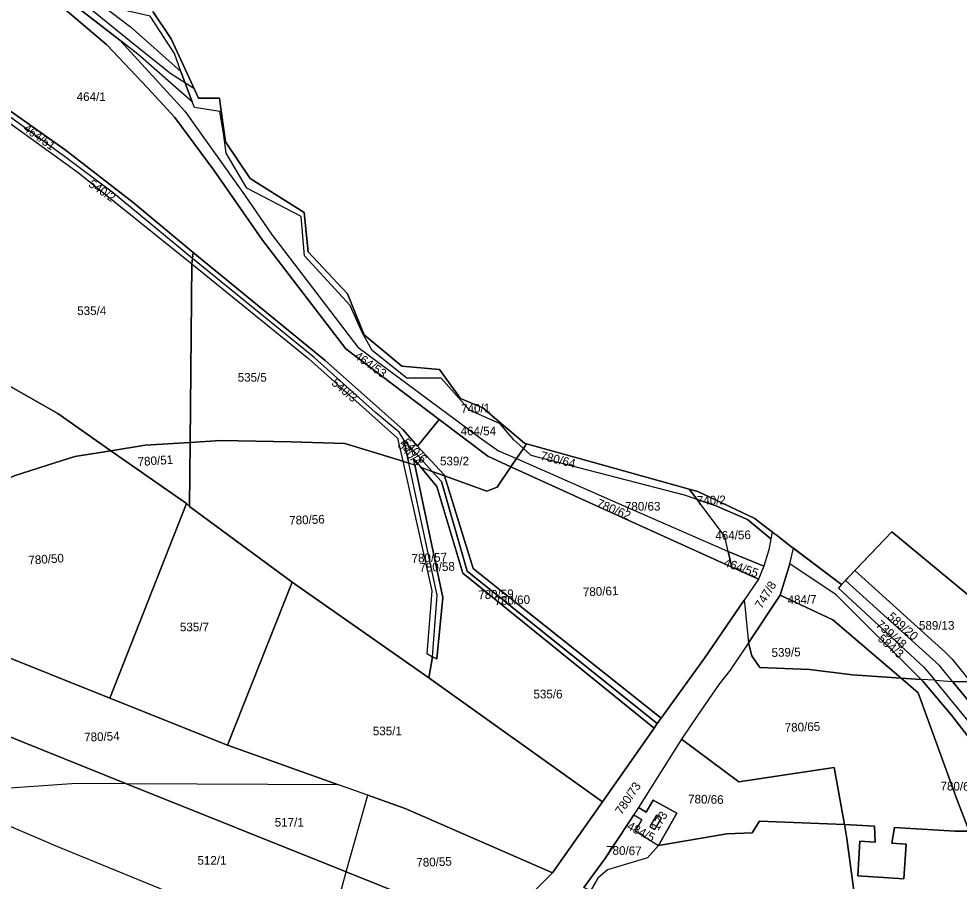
# Model space of a CAD drawing. Extents: x -629983 to -626385, y -1072828 to -1067897.
# Drawn here: x -627261.8 to -626936.7, y -1069848.5 to -1069550.4 of the extents above; entities that cross this region are included whole.
import ezdxf

# ---------------------------------------------------------------- set-up
doc = ezdxf.new("R2010")
doc.units = 0
for name, color, linetype in [('Parcela nároku', 7, 'Continuous'), ('Parcelní číslo', 7, 'Continuous'), ('Plocha PÚ', 7, 'Continuous'), ('Převzatý obvod_Vraclav', 7, 'Continuous'), ('voda', 7, 'Continuous')]:
    doc.layers.add(name, color=color, linetype=linetype)

msp = doc.modelspace()

# ---------------------------------------------------------------- linework, layer by layer
at = {"layer": 'Parcela nároku'}
for points in [[(-627194.37, -1069602.74), (-627177.63, -1069626.85), (-627148.72, -1069664.45), (-627116.5, -1069688.84), (-627123.94, -1069698.07), (-627129.03, -1069692.38), (-627155.86, -1069668.53), (-627201.56, -1069631.19), (-627222.35, -1069613.82), (-627245.87, -1069595.67), (-627265.56, -1069581.74), (-627277.42, -1069573.8), (-627317.22, -1069551.48), (-627328.12, -1069556.45), (-627334.48, -1069509.8), (-627316.09, -1069508.2), (-627271.98, -1069526.74), (-627249.67, -1069543.94), (-627231.46, -1069559.34), (-627217.34, -1069574.26), (-627207.91, -1069584.5)], [(-627235.71, -1069543.56), (-627223.24, -1069553.11), (-627205.83, -1069568.59), (-627201.84, -1069579.11), (-627220.68, -1069562.55), (-627226.86, -1069557.76), (-627251.28, -1069538.83), (-627283.19, -1069513.49), (-627268.22, -1069522.27), (-627246.36, -1069535.48)], [(-627258.69, -1069524.41), (-627268.22, -1069522.27), (-627246.36, -1069535.48), (-627235.71, -1069543.56), (-627223.24, -1069553.11), (-627205.83, -1069568.59), (-627207.95, -1069562.39), (-627216.37, -1069549.5), (-627228.1, -1069546.76), (-627233.41, -1069538.2), (-627242.45, -1069524.53), (-627248.62, -1069521.91)], [(-627204.46, -1069582.29), (-627183.77, -1069611.23), (-627174.51, -1069624.83), (-627144.63, -1069663.86), (-627102.68, -1069694.97), (-627095.92, -1069699.69), (-627089.72, -1069702.42), (-627091.65, -1069705.26), (-627099.6, -1069701.62), (-627116.5, -1069688.84), (-627148.72, -1069664.45), (-627177.63, -1069626.85), (-627194.37, -1069602.74), (-627207.91, -1069584.5), (-627217.34, -1069574.26), (-627231.46, -1069559.34), (-627249.67, -1069543.94), (-627271.98, -1069526.74), (-627274.18, -1069524.76), (-627251.28, -1069538.83), (-627226.86, -1069557.76)], [(-627317.22, -1069551.48), (-627277.42, -1069573.8), (-627265.56, -1069581.74), (-627245.87, -1069595.67), (-627222.35, -1069613.82), (-627201.56, -1069631.19), (-627201.8, -1069633.24), (-627229.1, -1069610.62), (-627246.09, -1069598), (-627266.23, -1069583.3), (-627285.91, -1069570.72), (-627317.17, -1069554.05), (-627327.83, -1069558.62), (-627328.12, -1069556.45)], [(-627095.42, -1069690.37), (-627106, -1069685.67), (-627115.82, -1069674.58), (-627127.62, -1069674.64), (-627139.64, -1069664.99), (-627143.1, -1069658.85), (-627147.21, -1069649.46), (-627163.08, -1069632.32), (-627164.24, -1069618.69), (-627182.98, -1069608.87), (-627190.13, -1069596.83), (-627190.91, -1069590.7), (-627192.35, -1069582.37), (-627201.1, -1069581.07), (-627201.84, -1069579.11), (-627220.68, -1069562.55), (-627226.86, -1069557.76), (-627204.46, -1069582.29), (-627183.77, -1069611.23), (-627174.51, -1069624.83), (-627144.63, -1069663.86), (-627102.68, -1069694.97), (-627095.92, -1069699.69), (-627089.72, -1069702.42), (-627087.33, -1069698.93), (-627090.63, -1069695.89)], [(-627229.1, -1069610.62), (-627246.09, -1069598), (-627266.23, -1069583.3), (-627266.23, -1069585.55), (-627241.35, -1069603.52), (-627202.04, -1069635.13), (-627201.8, -1069633.24)], [(-627266.23, -1069585.55), (-627241.35, -1069603.52), (-627202.04, -1069635.13), (-627202.64, -1069696.79), (-627218.16, -1069697.8), (-627230.03, -1069699.67), (-627248.4, -1069686.8), (-627265.16, -1069677.28), (-627265.26, -1069616.46)], [(-627128.72, -1069695.93), (-627130.35, -1069693.25), (-627138.52, -1069686.49), (-627159.67, -1069667.41), (-627201.8, -1069633.24), (-627202.04, -1069635.13), (-627161.63, -1069667.81), (-627130.84, -1069695.35), (-627129.05, -1069703.33), (-627126.99, -1069703.95)], [(-627201.8, -1069633.24), (-627201.56, -1069631.19), (-627155.86, -1069668.53), (-627129.03, -1069692.38), (-627123.94, -1069698.07), (-627114.7, -1069708.01), (-627114.58, -1069708.4), (-627118.86, -1069706.86), (-627128.72, -1069695.93), (-627130.35, -1069693.25), (-627138.52, -1069686.49), (-627159.67, -1069667.41)], [(-627161.63, -1069667.81), (-627130.84, -1069695.35), (-627129.05, -1069703.33), (-627149.14, -1069697.19), (-627167.71, -1069696.66), (-627192.07, -1069696.11), (-627202.64, -1069696.79), (-627202.04, -1069635.13)], [(-627291.19, -1069665.02), (-627265.16, -1069677.28), (-627248.4, -1069686.8), (-627230.03, -1069699.67), (-627242.51, -1069701.63), (-627251.94, -1069704.66), (-627263.41, -1069708.33), (-627281.71, -1069716.5), (-627302.54, -1069727.27), (-627313.07, -1069724.21)], [(-627116.5, -1069688.84), (-627099.6, -1069701.62), (-627091.65, -1069705.26), (-627096.48, -1069712.33), (-627099.99, -1069713.66), (-627114.58, -1069708.4), (-627114.7, -1069708.01), (-627123.94, -1069698.07)], [(-627124.87, -1069704.6), (-627125.31, -1069702.53), (-627122.87, -1069705.42), (-627118.86, -1069706.86), (-627128.72, -1069695.93), (-627126.99, -1069703.95)], [(-627230.03, -1069699.67), (-627218.16, -1069697.8), (-627202.64, -1069696.79), (-627202.85, -1069718.93), (-627203.9, -1069717.97)], [(-627149.14, -1069697.19), (-627129.05, -1069703.33), (-627118.97, -1069748.1), (-627120.76, -1069769.74), (-627118.81, -1069770.89), (-627120, -1069778.23), (-627167.33, -1069745.11), (-627202.85, -1069718.93), (-627202.64, -1069696.79), (-627192.07, -1069696.11), (-627167.71, -1069696.66)], [(-627084.67, -1069701.38), (-627087.33, -1069698.93), (-627089.72, -1069702.42), (-627056.59, -1069717), (-627018.85, -1069733.52), (-627016.5, -1069734.49), (-627017.66, -1069729.37), (-627027.28, -1069716.55), (-627031.63, -1069715.1), (-627054.85, -1069709.05)], [(-627068.42, -1069702.27), (-627029.99, -1069712.93), (-627027.28, -1069716.55), (-627031.63, -1069715.1), (-627054.85, -1069709.05), (-627084.67, -1069701.38), (-627087.33, -1069698.93), (-627086.24, -1069697.32)], [(-627281.71, -1069716.5), (-627263.41, -1069708.33), (-627251.94, -1069704.66), (-627242.51, -1069701.63), (-627230.03, -1069699.67), (-627203.9, -1069717.97), (-627230.37, -1069785.28), (-627292.84, -1069760.27), (-627294.17, -1069729.71), (-627302.54, -1069727.27)], [(-627091.65, -1069705.26), (-627089.72, -1069702.42), (-627056.59, -1069717), (-627018.85, -1069733.52), (-627016.5, -1069734.49), (-627015.27, -1069739.96), (-627062.1, -1069718.79)], [(-627118.97, -1069748.1), (-627120.76, -1069769.74), (-627118.81, -1069770.89), (-627117.15, -1069749.57), (-627126.99, -1069703.95), (-627129.05, -1069703.33)], [(-627118.81, -1069770.89), (-627117.15, -1069749.57), (-627126.99, -1069703.95), (-627124.87, -1069704.6), (-627115.21, -1069750.43), (-627117.27, -1069771.62)], [(-627122.87, -1069705.42), (-627117.24, -1069712.08), (-627108.34, -1069741.96), (-627042.19, -1069795.61), (-627059.96, -1069821.05), (-627120, -1069778.23), (-627118.81, -1069770.89), (-627117.27, -1069771.62), (-627115.21, -1069750.43), (-627124.87, -1069704.6), (-627125.31, -1069702.53)], [(-627106.85, -1069741.29), (-627041.07, -1069794.04), (-627042.19, -1069795.61), (-627108.34, -1069741.96), (-627117.24, -1069712.08), (-627122.87, -1069705.42), (-627118.86, -1069706.86), (-627115.73, -1069710.33)], [(-627015.27, -1069739.96), (-627006.03, -1069744.14), (-627011, -1069751.36), (-627024.78, -1069771.39), (-627039.76, -1069792.2), (-627094.34, -1069748.74), (-627104.74, -1069740.43), (-627114.58, -1069708.4), (-627099.99, -1069713.66), (-627096.48, -1069712.33), (-627091.65, -1069705.26), (-627062.1, -1069718.79)], [(-627118.86, -1069706.86), (-627114.58, -1069708.4), (-627104.74, -1069740.43), (-627094.34, -1069748.74), (-627039.76, -1069792.2), (-627041.07, -1069794.04), (-627106.85, -1069741.29), (-627115.73, -1069710.33)], [(-627029.99, -1069712.93), (-627027.09, -1069713.74), (-627007.36, -1069723.11), (-627005.01, -1069724.92), (-627001.28, -1069727.78), (-627001.75, -1069730.15), (-627009.83, -1069723.47), (-627020.99, -1069718.65), (-627027.28, -1069716.55)], [(-627202.85, -1069718.93), (-627167.33, -1069745.11), (-627189.71, -1069801.53), (-627230.37, -1069785.28), (-627203.9, -1069717.97)], [(-627020.99, -1069718.65), (-627009.83, -1069723.47), (-627001.75, -1069730.15), (-627002.5, -1069733.98), (-627004.25, -1069739.57), (-627016.5, -1069734.49), (-627017.66, -1069729.37), (-627027.28, -1069716.55)], [(-626993.96, -1069733.38), (-626994.96, -1069732.63), (-626997.8, -1069730.45), (-626999.93, -1069728.82), (-627000.36, -1069728.49), (-627001.28, -1069727.78), (-627001.75, -1069730.15), (-627002.5, -1069733.98), (-627004.25, -1069739.57), (-627006.03, -1069744.14), (-627011, -1069751.36), (-627010.81, -1069753.22), (-627009.77, -1069763.93), (-627009.55, -1069766.12), (-626998.59, -1069749.67), (-626995.22, -1069738.78)], [(-626959.97, -1069727.67), (-626972.76, -1069741.15), (-626941.46, -1069769.32), (-626939.04, -1069771.72), (-626932.72, -1069779.61), (-626917.9, -1069779.99), (-626910.52, -1069780.62), (-626918.56, -1069767.16), (-626927.26, -1069754.77)], [(-627016.5, -1069734.49), (-627004.25, -1069739.57), (-627006.03, -1069744.14), (-627015.27, -1069739.96)], [(-626978.44, -1069747.22), (-626948.86, -1069774.47), (-626945.1, -1069779.05), (-626949.8, -1069778.74), (-626979.25, -1069749.48), (-626995.22, -1069738.78), (-626993.96, -1069733.38), (-626977.33, -1069745.97)], [(-626949.8, -1069778.74), (-626979.25, -1069749.48), (-626995.22, -1069738.78), (-626998.59, -1069749.67), (-626980.4, -1069758.15), (-626956.76, -1069778.29)], [(-626941.46, -1069769.32), (-626939.04, -1069771.72), (-626932.72, -1069779.61), (-626938.99, -1069779.44), (-626943.46, -1069773.97), (-626976.01, -1069744.57), (-626972.76, -1069741.15)], [(-626976.01, -1069744.57), (-626977.33, -1069745.97), (-626978.44, -1069747.22), (-626948.86, -1069774.47), (-626945.1, -1069779.05), (-626938.99, -1069779.44), (-626943.46, -1069773.97)], [(-627120, -1069778.23), (-627059.96, -1069821.05), (-627077.28, -1069845.64), (-627128.21, -1069823.36), (-627141.19, -1069818.75), (-627151.32, -1069815.16), (-627189.71, -1069801.53), (-627167.33, -1069745.11)], [(-626998.59, -1069749.67), (-627009.55, -1069766.12), (-627008.4, -1069770.6), (-627005.63, -1069774.64), (-626988.44, -1069775.32), (-626973.5, -1069777.2), (-626956.76, -1069778.29), (-626980.4, -1069758.15)], [(-627230.37, -1069785.28), (-627189.71, -1069801.53), (-627151.32, -1069815.16), (-627224.57, -1069814.81), (-627281.95, -1069791.81), (-627289.72, -1069770.53), (-627292.84, -1069760.27)], [(-627015.81, -1069775.51), (-627019.72, -1069780.51), (-627027.18, -1069791.27), (-627032.66, -1069799.39), (-627012.86, -1069814.18), (-626979.87, -1069809.23), (-626976.36, -1069828.87), (-626965.93, -1069829.51), (-626965.75, -1069834.99), (-626970.99, -1069834.66), (-626971.74, -1069846.69), (-626955.77, -1069847.69), (-626955.02, -1069835.66), (-626959.98, -1069835.35), (-626958.99, -1069829.94), (-626938.2, -1069831.22), (-626933.22, -1069831.22), (-626937.47, -1069820.18), (-626950.84, -1069783.33), (-626956.76, -1069778.29), (-626973.5, -1069777.2), (-626988.44, -1069775.32), (-627005.63, -1069774.64), (-627008.4, -1069770.6), (-627009.55, -1069766.12)], [(-626920.52, -1069815.29), (-626939.29, -1069791.15), (-626949.21, -1069779.33), (-626949.8, -1069778.74), (-626956.76, -1069778.29), (-626950.84, -1069783.33), (-626937.47, -1069820.18), (-626933.22, -1069831.22), (-626927.26, -1069831.22), (-626918.28, -1069831.86)], [(-626913.9, -1069832.18), (-626914.03, -1069830.33), (-626915.9, -1069814.62), (-626945.1, -1069779.05), (-626949.8, -1069778.74), (-626949.21, -1069779.33), (-626939.29, -1069791.15), (-626920.52, -1069815.29), (-626918.28, -1069831.86)], [(-626945.1, -1069779.05), (-626938.99, -1069779.44), (-626929.34, -1069791.26), (-626911.78, -1069813.19), (-626909.69, -1069832.48), (-626913.9, -1069832.18), (-626914.03, -1069830.33), (-626915.9, -1069814.62)], [(-626906.83, -1069812.73), (-626900.65, -1069834.25), (-626905.52, -1069832.84), (-626911.78, -1069813.19), (-626929.34, -1069791.26), (-626938.99, -1069779.44), (-626932.72, -1069779.61), (-626928.52, -1069784.84), (-626909.14, -1069809.25)], [(-627281.95, -1069791.81), (-627224.57, -1069814.81), (-627241.92, -1069814.72), (-627271.63, -1069816.83)], [(-626976.36, -1069828.87), (-626979.87, -1069809.23), (-627012.86, -1069814.18), (-627032.66, -1069799.39), (-627047.6, -1069823.01), (-627044.92, -1069824.67), (-627042.48, -1069820.54), (-627034.32, -1069824.97), (-627040.67, -1069836.11), (-627016.96, -1069832.15), (-627008.21, -1069831.82), (-627005.67, -1069827.71)], [(-627241.92, -1069814.72), (-627271.63, -1069816.83), (-627267.94, -1069825.76), (-627267.83, -1069828.17), (-627248.42, -1069836.5), (-627155.18, -1069874.63), (-627154, -1069869.04), (-627150.4, -1069851.72), (-627148.6, -1069845.26), (-627224.57, -1069814.81)], [(-627151.32, -1069815.16), (-627224.57, -1069814.81), (-627148.6, -1069845.26), (-627141.19, -1069818.75)], [(-627128.21, -1069823.36), (-627077.28, -1069845.64), (-627090.95, -1069859.46), (-627098.75, -1069866.3), (-627124.51, -1069854.91), (-627148.6, -1069845.26), (-627141.19, -1069818.75)], [(-627047.6, -1069823.01), (-627049.2, -1069825.55), (-627046.42, -1069827.19), (-627048.74, -1069831.11), (-627040.67, -1069836.11), (-627034.32, -1069824.97), (-627042.48, -1069820.54), (-627044.92, -1069824.67)], [(-627059.25, -1069840.82), (-627050.65, -1069827.83), (-627049.2, -1069825.55), (-627046.42, -1069827.19), (-627048.74, -1069831.11), (-627040.67, -1069836.11), (-627044.48, -1069840.42), (-627058.25, -1069844.55), (-627061.64, -1069847.48), (-627064.17, -1069851.84), (-627066.48, -1069850.71)], [(-627043.6, -1069829.61), (-627041.92, -1069830.59), (-627039.65, -1069826.69), (-627041.33, -1069825.7)], [(-627043.6, -1069829.61), (-627041.92, -1069830.59), (-627039.65, -1069826.69), (-627041.33, -1069825.7)], [(-627267.83, -1069828.17), (-627248.42, -1069836.5), (-627155.18, -1069874.63), (-627159.39, -1069894.65), (-627163.63, -1069926.9), (-627217.96, -1069905.51), (-627279.93, -1069882.21), (-627274.63, -1069868.47), (-627269.77, -1069852.06)], [(-627005.67, -1069827.71), (-627008.21, -1069831.82), (-627016.96, -1069832.15), (-627040.67, -1069836.11), (-627044.48, -1069840.42), (-627058.25, -1069844.55), (-627061.64, -1069847.48), (-627064.17, -1069851.84), (-627010.49, -1069878.16), (-626966.86, -1069898.03), (-626975.49, -1069833.73), (-626976.36, -1069828.87)], [(-626955.02, -1069835.66), (-626955.77, -1069847.69), (-626971.74, -1069846.69), (-626970.99, -1069834.66), (-626965.75, -1069834.99), (-626965.93, -1069829.51), (-626976.36, -1069828.87), (-626975.49, -1069833.73), (-626966.86, -1069898.03), (-626939.89, -1069913.2), (-626931.2, -1069914.54), (-626927.45, -1069886.65), (-626924.22, -1069854.62), (-626933.22, -1069831.22), (-626938.2, -1069831.22), (-626958.99, -1069829.94), (-626959.98, -1069835.35)], [(-627154, -1069869.04), (-627150.4, -1069851.72), (-627148.6, -1069845.26), (-627124.51, -1069854.91), (-627098.75, -1069866.3), (-627116.79, -1069882.11), (-627123.18, -1069887.72), (-627155.18, -1069874.63)]]:
    msp.add_lwpolyline(points, close=True, dxfattribs=at)
for points in [[(-627215.5, -1069547.88), (-627209.13, -1069557.24), (-627202.91, -1069570.81), (-627199.72, -1069577.78), (-627195.15, -1069577.77), (-627192.47, -1069577.76), (-627192.08, -1069580.52), (-627190.56, -1069591.18), (-627190.32, -1069592.88), (-627181.83, -1069605.56), (-627163.16, -1069617.37), (-627161.83, -1069630.91), (-627148.2, -1069645.4), (-627142.43, -1069659.62), (-627129.41, -1069670.46), (-627116.41, -1069671.64), (-627109.14, -1069681.61), (-627101.33, -1069684.9), (-627094.19, -1069690.98), (-627086.99, -1069697.11), (-627086.24, -1069697.32), (-627087.33, -1069698.93), (-627090.63, -1069695.89), (-627095.42, -1069690.37), (-627106, -1069685.67), (-627115.82, -1069674.58), (-627127.62, -1069674.64), (-627139.64, -1069664.99), (-627143.1, -1069658.85), (-627147.21, -1069649.46), (-627163.08, -1069632.32), (-627164.24, -1069618.69), (-627182.98, -1069608.87), (-627190.13, -1069596.83), (-627190.91, -1069590.7), (-627192.35, -1069582.37), (-627201.1, -1069581.07), (-627201.84, -1069579.11), (-627205.83, -1069568.59), (-627207.95, -1069562.39), (-627216.37, -1069549.5)], [(-627090.95, -1069859.46), (-627077.28, -1069845.64), (-627059.96, -1069821.05), (-627042.19, -1069795.61), (-627041.07, -1069794.04), (-627039.76, -1069792.2), (-627024.78, -1069771.39), (-627011, -1069751.36), (-627010.81, -1069753.22), (-627009.77, -1069763.93), (-627009.55, -1069766.12), (-627015.81, -1069775.51), (-627019.72, -1069780.51), (-627027.18, -1069791.27), (-627032.66, -1069799.39), (-627047.6, -1069823.01), (-627049.2, -1069825.55), (-627050.65, -1069827.83), (-627059.25, -1069840.82), (-627066.48, -1069850.71)]]:
    msp.add_lwpolyline(points, dxfattribs=at)
at = {"layer": 'Plocha PÚ'}
msp.add_lwpolyline([(-626927.26, -1069754.77), (-626959.97, -1069727.67), (-626972.76, -1069741.15), (-626976.01, -1069744.57), (-626977.33, -1069745.97), (-626993.96, -1069733.38), (-626994.96, -1069732.63), (-626997.8, -1069730.45), (-626999.93, -1069728.82), (-627000.36, -1069728.49), (-627001.28, -1069727.78), (-627005.01, -1069724.92), (-627007.36, -1069723.11), (-627027.09, -1069713.74), (-627029.99, -1069712.93), (-627068.42, -1069702.27), (-627086.24, -1069697.32), (-627086.99, -1069697.11), (-627094.19, -1069690.98), (-627101.33, -1069684.9), (-627109.14, -1069681.61), (-627116.41, -1069671.64), (-627129.41, -1069670.46), (-627142.43, -1069659.62), (-627148.2, -1069645.4), (-627161.83, -1069630.91), (-627163.16, -1069617.37), (-627181.83, -1069605.56), (-627190.32, -1069592.88), (-627190.56, -1069591.18), (-627192.08, -1069580.52), (-627192.47, -1069577.76), (-627195.15, -1069577.77), (-627199.72, -1069577.78), (-627202.91, -1069570.81), (-627209.13, -1069557.24), (-627215.5, -1069547.88)], dxfattribs=at)
at = {"layer": 'Převzatý obvod_Vraclav'}
msp.add_lwpolyline([(-627215.5, -1069547.88), (-627209.13, -1069557.24), (-627202.91, -1069570.81), (-627199.72, -1069577.78), (-627195.15, -1069577.77), (-627192.47, -1069577.76), (-627192.08, -1069580.52), (-627190.56, -1069591.18), (-627190.32, -1069592.88), (-627181.83, -1069605.56), (-627163.16, -1069617.37), (-627161.83, -1069630.91), (-627148.2, -1069645.4), (-627142.43, -1069659.62), (-627129.41, -1069670.46), (-627116.41, -1069671.64), (-627109.14, -1069681.61), (-627101.33, -1069684.9), (-627094.19, -1069690.98), (-627086.99, -1069697.11), (-627086.24, -1069697.32), (-627068.42, -1069702.27), (-627029.99, -1069712.93), (-627027.09, -1069713.74), (-627007.36, -1069723.11), (-627005.01, -1069724.92), (-626999.93, -1069728.82), (-626997.8, -1069730.45), (-626994.96, -1069732.63), (-626977.33, -1069745.97), (-626959.97, -1069727.67), (-626927.26, -1069754.77)], dxfattribs=at)
at = {"layer": 'voda'}
msp.add_lwpolyline([(-627608.69, -1069228.58), (-627567.33, -1069271.37), (-627536.18, -1069303.59), (-627504.31, -1069334.27), (-627485.76, -1069353.94), (-627464.97, -1069374.06), (-627447.22, -1069392.83), (-627416.71, -1069421.47), (-627386.71, -1069452.38), (-627377.38, -1069459.57), (-627356.25, -1069473.06), (-627328.64, -1069489.76), (-627308.58, -1069501.31), (-627278, -1069518.91), (-627267.24, -1069526.16), (-627251.07, -1069535.67), (-627238.49, -1069545.79), (-627221.22, -1069559.68), (-627209.33, -1069569.24), (-627201.32, -1069574.3)], dxfattribs=at)

# ---------------------------------------------------------------- texts
at = {"layer": 'Parcelní číslo'}
for s, p in [('464/1', (-627241.83, -1069578.78)), ('535/4', (-627241.64, -1069652.78)), ('535/5', (-627186.14, -1069675.81)), ('464/54', (-627109.07, -1069694.35)), ('539/2', (-627116.19, -1069704.76)), ('535/7', (-627206.13, -1069762.12)), ('589/13', (-626950.56, -1069761.57)), ('535/6', (-627083.87, -1069785.31)), ('535/1', (-627139.42, -1069798.06)), ('517/1', (-627173.35, -1069829.64)), ('512/1', (-627200.07, -1069842.8))]:
    msp.add_text(s, height=3, dxfattribs=at).set_placement(p)
for s, rotation, p in [('464/51', 324.5428, (-627260.54, -1069588.9)), ('540/2', 325.6259, (-627238.02, -1069608.15)), ('464/53', 324.6599, (-627146.06, -1069667.57)), ('540/3', 319.8505, (-627153.99, -1069676.64)), ('740/1', 1.3178, (-627108.86, -1069686.65)), ('540/6', 314.7257, (-627129.53, -1069697.14)), ('540/4', 312.4912, (-627131.08, -1069697.89)), ('780/51', 3.7242, (-627220.65, -1069705)), ('780/64', 346.1811, (-627081.67, -1069702.73)), ('740/2', 1.3178, (-627027.35, -1069718.4)), ('780/62', 337.243, (-627062.31, -1069718.95)), ('780/63', 0.2291, (-627052.24, -1069720.43)), ('780/56', 2.12, (-627168.29, -1069725.28)), ('464/56', 1.3178, (-627020.94, -1069730.52)), ('780/57', 2.12, (-627125.97, -1069738.4)), ('780/50', 3.7242, (-627258.43, -1069739.06)), ('780/58', 2.12, (-627123.27, -1069741.59)), ('464/55', 340.7099, (-627018.31, -1069739.51)), ('780/59', 2.12, (-627102.91, -1069751.04)), ('780/61', 2.12, (-627066.73, -1069750.03)), ('747/8', 58.4417, (-627004.98, -1069754.54)), ('780/60', 2.12, (-627097.26, -1069753.06)), ('484/7', 1.3178, (-626995.96, -1069752.75)), ('589/20', 318.851, (-626961.72, -1069757.44)), ('739/48', 318.851, (-626965.72, -1069760.21)), ('584/3', 318.851, (-626965.04, -1069765.06)), ('539/5', 1.3178, (-627001.51, -1069770.98)), ('780/65', 2.1773, (-626996.93, -1069796.93)), ('780/54', 2.12, (-627239.19, -1069800.23)), ('780/73', 56.3217, (-627053.37, -1069825.75)), ('780/68', 358.9581, (-626943.14, -1069817.08)), ('780/66', 358.9581, (-627030.42, -1069821.57)), ('173', 59.0146, (-627040.78, -1069831.25)), ('484/5', 332.6318, (-627051.79, -1069830.4)), ('780/67', 358.9581, (-627058.78, -1069839.32)), ('780/55', 2.12, (-627124.32, -1069843.57))]:
    msp.add_text(s, height=3, rotation=rotation, dxfattribs=at).set_placement(p)

doc.saveas('drawing.dxf')
